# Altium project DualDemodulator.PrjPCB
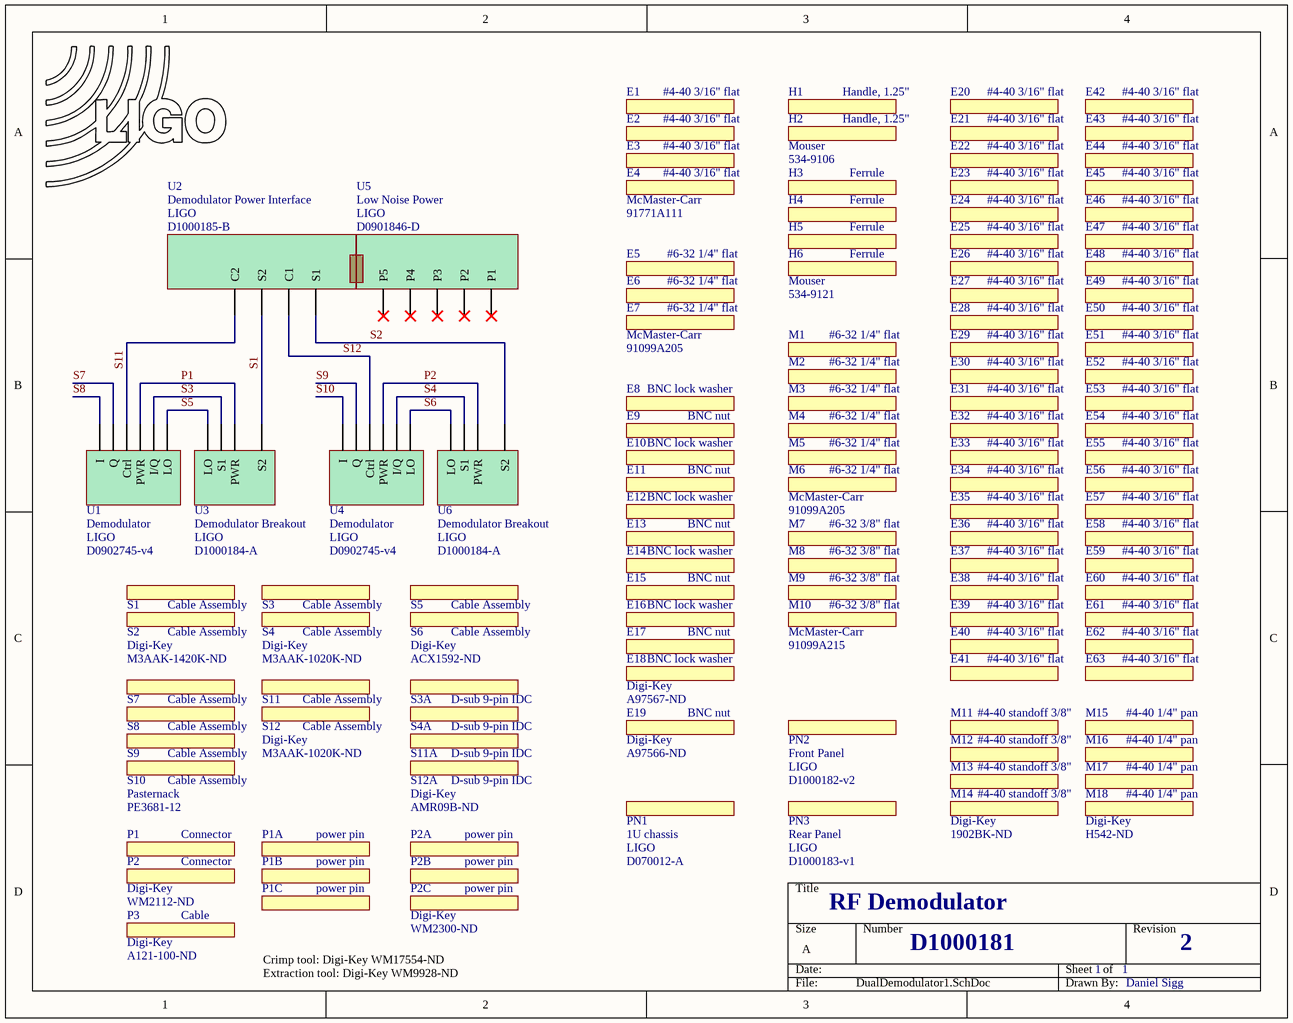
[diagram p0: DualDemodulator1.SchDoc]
1 sheet, 122 parts. Net scope: global (net labels, ports and power ports of the same name join across sheets).

## Sheet DualDemodulator1.SchDoc: D1000181
size A; Engineer: Daniel Sigg; Revision: 2; PageSetup: Record=PageOptions|CenterHorizontal=True|CenterVertical=True|PrintScale=1.12|XCorrection=1.00|YCorrection=1.00|PrintKind=0|BorderSize=5000000|LeftOffset=0|BottomOffset=0|Orientation=2|PaperLength=1000|PaperWidth=1000|Scale=100|PaperSource=7|PrintQuality=-4|MediaType=1|DitherType=10|PaperKind=Letter|PrintScaleMode=1

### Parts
E1  #4-40 3/16" flat  (mechanical)
E2  #4-40 3/16" flat  (mechanical)
E3  #4-40 3/16" flat  (mechanical)
E4  #4-40 3/16" flat  Part Number: 91771A111  Distributor: McMaster-Carr  (mechanical)
E5  #6-32 1/4" flat  (mechanical)
E6  #6-32 1/4" flat  (mechanical)
E7  #6-32 1/4" flat  Part Number: 91099A205  Distributor: McMaster-Carr  (mechanical)
E8  BNC lock washer  (mechanical)
E9  BNC nut  (mechanical)
E10  BNC lock washer  (mechanical)
E11  BNC nut  (mechanical)
E12  BNC lock washer  (mechanical)
E13  BNC nut  (mechanical)
E14  BNC lock washer  (mechanical)
E15  BNC nut  (mechanical)
E16  BNC lock washer  (mechanical)
E17  BNC nut  (mechanical)
E18  BNC lock washer  Part Number: A97567-ND  Distributor: Digi-Key  (mechanical)
E19  BNC nut  Part Number: A97566-ND  Distributor: Digi-Key  (mechanical)
E20  #4-40 3/16" flat  (mechanical)
E21  #4-40 3/16" flat  (mechanical)
E22  #4-40 3/16" flat  (mechanical)
E23  #4-40 3/16" flat  (mechanical)
E24  #4-40 3/16" flat  (mechanical)
E25  #4-40 3/16" flat  (mechanical)
E26  #4-40 3/16" flat  (mechanical)
E27  #4-40 3/16" flat  (mechanical)
E28  #4-40 3/16" flat  (mechanical)
E29  #4-40 3/16" flat  (mechanical)
E30  #4-40 3/16" flat  (mechanical)
E31  #4-40 3/16" flat  (mechanical)
E32  #4-40 3/16" flat  (mechanical)
E33  #4-40 3/16" flat  (mechanical)
E34  #4-40 3/16" flat  (mechanical)
E35  #4-40 3/16" flat  (mechanical)
E36  #4-40 3/16" flat  (mechanical)
E37  #4-40 3/16" flat  (mechanical)
E38  #4-40 3/16" flat  (mechanical)
E39  #4-40 3/16" flat  (mechanical)
E40  #4-40 3/16" flat  (mechanical)
E41  #4-40 3/16" flat  (mechanical)
E42  #4-40 3/16" flat  (mechanical)
E43  #4-40 3/16" flat  (mechanical)
E44  #4-40 3/16" flat  (mechanical)
E45  #4-40 3/16" flat  (mechanical)
E46  #4-40 3/16" flat  (mechanical)
E47  #4-40 3/16" flat  (mechanical)
E48  #4-40 3/16" flat  (mechanical)
E49  #4-40 3/16" flat  (mechanical)
E50  #4-40 3/16" flat  (mechanical)
E51  #4-40 3/16" flat  (mechanical)
E52  #4-40 3/16" flat  (mechanical)
E53  #4-40 3/16" flat  (mechanical)
E54  #4-40 3/16" flat  (mechanical)
E55  #4-40 3/16" flat  (mechanical)
E56  #4-40 3/16" flat  (mechanical)
E57  #4-40 3/16" flat  (mechanical)
E58  #4-40 3/16" flat  (mechanical)
E59  #4-40 3/16" flat  (mechanical)
E60  #4-40 3/16" flat  (mechanical)
E61  #4-40 3/16" flat  (mechanical)
E62  #4-40 3/16" flat  (mechanical)
E63  #4-40 3/16" flat  (mechanical)
H1  Handle, 1.25"  (mechanical)
H2  Handle, 1.25"  Part Number: 534-9106  Distributor: Mouser  (mechanical)
H3  Ferrule  (mechanical)
H4  Ferrule  (mechanical)
H5  Ferrule  (mechanical)
H6  Ferrule  Part Number: 534-9121  Distributor: Mouser  (mechanical)
LOGO1  LIGO logo  [LIGO_LOGO]  (value not drawn)  (no BOM)
M1  #6-32 1/4" flat  (mechanical)
M2  #6-32 1/4" flat  (mechanical)
M3  #6-32 1/4" flat  (mechanical)
M4  #6-32 1/4" flat  (mechanical)
M5  #6-32 1/4" flat  (mechanical)
M6  #6-32 1/4" flat  Part Number: 91099A205  Distributor: McMaster-Carr  (mechanical)
M7  #6-32 3/8" flat  (mechanical)
M8  #6-32 3/8" flat  (mechanical)
M9  #6-32 3/8" flat  (mechanical)
M10  #6-32 3/8" flat  Part Number: 91099A215  Distributor: McMaster-Carr  (mechanical)
M11  #4-40 standoff 3/8"  (mechanical)
M12  #4-40 standoff 3/8"  (mechanical)
M13  #4-40 standoff 3/8"  (mechanical)
M14  #4-40 standoff 3/8"  Part Number: 1902BK-ND  Distributor: Digi-Key  (mechanical)
M15  #4-40 1/4" pan  (mechanical)
M16  #4-40 1/4" pan  (mechanical)
M17  #4-40 1/4" pan  (mechanical)
M18  #4-40 1/4" pan  Part Number: H542-ND  Distributor: Digi-Key  (mechanical)
P1  Connector  (mechanical)
P1A  power pin  (mechanical)
P1B  power pin  (mechanical)
P1C  power pin  (mechanical)
P2  Connector  Part Number: WM2112-ND  Distributor: Digi-Key  (mechanical)
P2A  power pin  (mechanical)
P2B  power pin  (mechanical)
P2C  power pin  Part Number: WM2300-ND  Distributor: Digi-Key  (mechanical)
P3  Cable  Part Number: A121-100-ND  Distributor: Digi-Key  (mechanical)
PN1  1U chassis  Part Number: D070012-A  Distributor: LIGO  (mechanical)
PN2  Front Panel  Part Number: D1000182-v2  Distributor: LIGO  (mechanical)
PN3  Rear Panel  Part Number: D1000183-v1  Distributor: LIGO  (mechanical)
S1  Cable Assembly  (mechanical)
S2  Cable Assembly  Part Number: M3AAK-1420K-ND  Distributor: Digi-Key  (mechanical)
S3  Cable Assembly  (mechanical)
S3A  D-sub 9-pin IDC  (mechanical)
S4  Cable Assembly  Part Number: M3AAK-1020K-ND  Distributor: Digi-Key  (mechanical)
S4A  D-sub 9-pin IDC  (mechanical)
S5  Cable Assembly  (mechanical)
S6  Cable Assembly  Part Number: ACX1592-ND  Distributor: Digi-Key  (mechanical)
S7  Cable Assembly  (mechanical)
S8  Cable Assembly  (mechanical)
S9  Cable Assembly  (mechanical)
S10  Cable Assembly  Part Number: PE3681-12  Distributor: Pasternack  (mechanical)
S11  Cable Assembly  (mechanical)
S11A  D-sub 9-pin IDC  (mechanical)
S12  Cable Assembly  Part Number: M3AAK-1020K-ND  Distributor: Digi-Key  (mechanical)
S12A  D-sub 9-pin IDC  Part Number: AMR09B-ND  Distributor: Digi-Key  (mechanical)
U1  Demodulator  Distributor: LIGO  Part Number: D0902745-v4
U2  Demodulator Power Interface  Distributor: LIGO  Part Number: D1000185-B
U3  Demodulator Breakout  Distributor: LIGO  Part Number: D1000184-A
U4  Demodulator  Distributor: LIGO  Part Number: D0902745-v4
U5  Low Noise Power  Distributor: LIGO  Part Number: D0901846-D
U6  Demodulator Breakout  Distributor: LIGO  Part Number: D1000184-A

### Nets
P1: U1.1(PWR) U3.1(PWR)
P2: U4.1(PWR) U6.1(PWR)
S1: U2.3(S2) U3.4(S2)
S2: U2.1(S1) U6.4(S2)
S3: U1.2(I/Q) U3.2(S1)
S4: U4.2(I/Q) U6.2(S1)
S5: U1.3(LO) U3.3(LO)
S6: U4.3(LO) U6.3(LO)
S7: U1.5(Q)
S8: U1.4(I)
S9: U4.5(Q)
S10: U4.4(I)
S11: U1.6(Ctrl) U2.4(C2)
S12: U2.2(C1) U4.6(Ctrl)

Not connected (* = marked no-connect by the designer): U5 1(P1)* 2(P2)* 3(P3)* 4(P4)* 5(P5)*

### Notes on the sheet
- RF Demodulator
- Crimp tool: Digi-Key WM17554-ND
  Extraction tool: Digi-Key WM9928-ND
- D1000181
- 1
- 2
- Daniel Sigg

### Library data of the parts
E1-E3 E20-E63 = Partlist: #4-40 3/16" flat head screw; Part Number: 91771A111
E4 = Partlist: #4-40 3/16" flat head screw
E5 E6 M1-M5 = Partlist: #6-32 1/4" flat head screw; Part Number: 91099A205
E7 M6 = Partlist: #6-32 1/4" flat head screw
E8 E10 E12 E14 E16 = Partlist: Part Number: A97567-ND
E9 E11 E13 E15 E17 = Partlist: Part Number: A97566-ND
E18 E19 H6 = Partlist
H1 = Partlist: Rack handle 2U; Part Number: 534-9106
H2 = Partlist: Rack handle 2U
H3-H5 = Partlist: Part Number: 534-9121
LOGO1 = LIGO_logo
M7-M9 = Partlist: #6-32 3/8" flat head screw; Part Number: 91099A215
M10 M14 M18 = Partlist: #6-32 3/8" flat head screw
M11-M13 = Partlist: #6-32 3/8" flat head screw; Part Number: 1902BK-ND
M15-M17 = Partlist: #6-32 3/8" flat head screw; Part Number: H542-ND
P1 = Partlist: Molex Connector; Part Number: WM2112-ND
P1A P1B P1C P2A P2B = Partlist: Molex power pin; Part Number: WM2300-ND
P2 = Partlist: Molex Connector
P2C = Partlist: Molex power pin
P3 = Partlist: Multiconductor cable, 100'
PN1 = Partlist: chassis
PN2 PN3 = Partlist: panel
S1 = Partlist: Cable; Part Number: M3AAK-1420K-ND
S2 S4 S6 S10 S12 = Partlist: Cable
S3 S11 = Partlist: Cable; Part Number: M3AAK-1020K-ND
S3A S4A S11A = Partlist: D-sub 9-pin flat ribbon, male; Part Number: AMR09B-ND
S5 = Partlist: Cable; Part Number: ACX1592-ND
S7-S9 = Partlist: Cable; Part Number: PE3681-12
S12A = Partlist: D-sub 9-pin flat ribbon, male
U1 U4 = Demodulator2: RF demodulator
U2 = DemodulatorPowerInterface2
U3 U6 = DemodulatorBreakout
U5 = LowNoisePower: Low Noise Power Board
